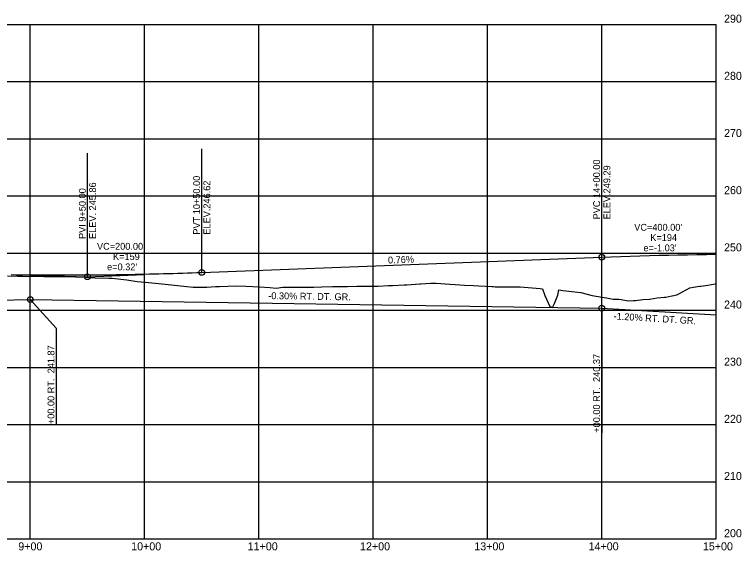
# Model space of a CAD drawing. Extents: x 1939726 to 1943270, y 529766 to 530234.
# Drawn here: x 1940634 to 1941270, y 529766 to 530234 of the extents above; entities that cross this region are included whole.
import ezdxf

# ---------------------------------------------------------------- set-up
doc = ezdxf.new("R2010")
doc.units = 0
for name, color, linetype in [('R_Axis', 7, 'Continuous'), ('R_Axis Annot', 7, 'Continuous'), ('R_Exist Surface', 7, 'Continuous'), ('R_Grid', 7, 'Continuous'), ('R_Vert Alg', 7, 'Continuous'), ('R_Vert Alg Annot', 7, 'Continuous')]:
    doc.layers.add(name, color=color, linetype=linetype)

msp = doc.modelspace()

# ---------------------------------------------------------------- linework, layer by layer
at = {"layer": 'R_Axis'}
for p, q in [((1941247.77, 529775.76), (1941247.77, 530225.76)), ((1939747.77, 529775.76), (1941247.77, 529775.76))]:
    msp.add_line(p, q, dxfattribs=at)
at = {"layer": 'R_Exist Surface'}
msp.add_lwpolyline([(1940627.77, 530005.8), (1940636.75, 530005.67), (1940640.9, 530005.6), (1940659.63, 530005.31), (1940664.83, 530005.26), (1940687.25, 530004.95), (1940687.86, 530004.95), (1940688.32, 530004.94), (1940691.25, 530004.9), (1940704.34, 530004.01), (1940716.35, 530003.94), (1940719.27, 530003.83), (1940732.12, 530002.43), (1940741.34, 530001), (1940748.42, 530000.24), (1940765.86, 529998.64), (1940784.61, 529996.48), (1940790.29, 529995.93), (1940802.24, 529995.86), (1940809.92, 529996.46), (1940813.31, 529996.37), (1940827.78, 529997.04), (1940836.26, 529996.77), (1940848.19, 529996.17), (1940857.32, 529995.78), (1940862.81, 529995.19), (1940868.85, 529995.97), (1940880.27, 529995.8), (1940885.88, 529995.98), (1940895.89, 529995.85), (1940902.97, 529996.15), (1940912.22, 529996.48), (1940925.27, 529996.47), (1940933.34, 529996.7), (1940947.49, 529996.7), (1940952.2, 529996.78), (1940961.16, 529997.29), (1940964.65, 529997.36), (1940974.86, 529997.97), (1940977.1, 529998.02), (1940988.59, 529998.76), (1940989.53, 529998.78), (1940998.16, 529999.37), (1941002.29, 529999.53), (1941002.96, 529999.49), (1941014.89, 529998.62), (1941019.38, 529998.36), (1941027.58, 529997.79), (1941035.53, 529997.36), (1941040.35, 529997.05), (1941051.46, 529996.48), (1941053.2, 529996.37), (1941054.47, 529996.33), (1941074.38, 529996.18), (1941074.49, 529996.18), (1941076.43, 529996.17), (1941093.85, 529994.83), (1941096.03, 529994.5), (1941097.97, 529988.68), (1941102.22, 529978.97), (1941104.74, 529978.09), (1941106.43, 529981.74), (1941109.22, 529988.81), (1941110.27, 529993.58), (1941113.6, 529992.96), (1941129.61, 529991.18), (1941139.51, 529988.51), (1941149.85, 529987.03), (1941151.94, 529986.62), (1941157.76, 529985.53), (1941158.28, 529985.51), (1941162.61, 529985.38), (1941164.62, 529985.03), (1941170.96, 529984.06), (1941170.98, 529984.06), (1941175.58, 529984.14), (1941177.31, 529984.32), (1941183.62, 529985.15), (1941183.65, 529985.15), (1941189.42, 529985.48), (1941189.99, 529985.56), (1941196.33, 529986.58), (1941196.37, 529986.59), (1941202.67, 529987.16), (1941203.77, 529987.29), (1941209.02, 529988.27), (1941209.3, 529988.33), (1941213.39, 529989.18), (1941215.36, 529990.22), (1941221.7, 529993.7), (1941224.71, 529995.43), (1941228.04, 529995.92), (1941231.69, 529996.47), (1941233.62, 529996.71), (1941234.38, 529996.82), (1941240.72, 529997.78), (1941247.07, 529998.77), (1941247.77, 529998.88)], dxfattribs=at)
at = {"layer": 'R_Grid'}
for p, q in [((1939747.77, 530225.76), (1941247.77, 530225.76)), ((1939747.77, 530225.76), (1941247.77, 530225.76)), ((1940647.77, 529775.76), (1940647.77, 530225.76)), ((1940747.77, 529775.76), (1940747.77, 530225.76)), ((1940847.77, 529775.76), (1940847.77, 530225.76)), ((1940947.77, 529775.76), (1940947.77, 530225.76)), ((1941047.77, 529775.76), (1941047.77, 530225.76)), ((1941147.77, 529775.76), (1941147.77, 530225.76)), ((1939747.77, 530175.76), (1941247.77, 530175.76)), ((1939747.77, 530125.76), (1941247.77, 530125.76)), ((1939747.77, 530075.76), (1941247.77, 530075.76)), ((1939747.77, 530025.76), (1941247.77, 530025.76)), ((1939747.77, 529975.76), (1941247.77, 529975.76)), ((1939747.77, 529925.76), (1941247.77, 529925.76)), ((1939747.77, 529875.76), (1941247.77, 529875.76)), ((1939747.77, 529825.76), (1941247.77, 529825.76))]:
    msp.add_line(p, q, dxfattribs=at)
at = {"layer": 'R_Vert Alg'}
for p, q in [((1940797.77, 530008.86), (1941147.77, 530022.19)), ((1940647.77, 530006.31), (1940697.77, 530005.06)), ((1940697.77, 530005.06), (1940747.77, 530006.96)), ((1940147.77, 529975.11), (1940647.77, 529985.11)), ((1940647.77, 529985.11), (1941147.77, 529977.61)), ((1941147.77, 529977.61), (1941247.77, 529971.61))]:
    msp.add_line(p, q, dxfattribs=at)
for points in [[(1941147.77, 530022.19), (1941156.1, 530022.5), (1941164.43, 530022.79), (1941172.77, 530023.06), (1941181.1, 530023.32), (1941189.43, 530023.55), (1941197.77, 530023.77), (1941206.1, 530023.97), (1941214.43, 530024.16), (1941222.77, 530024.32), (1941231.1, 530024.47), (1941239.43, 530024.6), (1941247.77, 530024.71)], [(1940631.1, 530006.9), (1940635.27, 530006.84), (1940639.43, 530006.79), (1940643.6, 530006.74), (1940647.77, 530006.7), (1940651.93, 530006.66), (1940656.1, 530006.63), (1940660.27, 530006.61), (1940664.43, 530006.59), (1940668.6, 530006.58), (1940672.77, 530006.57), (1940676.93, 530006.57), (1940681.1, 530006.57), (1940685.27, 530006.58), (1940689.43, 530006.59), (1940693.6, 530006.61), (1940701.93, 530006.66), (1940706.1, 530006.7), (1940710.27, 530006.74), (1940714.43, 530006.79), (1940718.6, 530006.84), (1940722.77, 530006.9), (1940726.93, 530006.96), (1940731.1, 530007.03), (1940735.27, 530007.1), (1940739.43, 530007.18), (1940743.6, 530007.26), (1940747.77, 530007.35), (1940751.93, 530007.45), (1940756.1, 530007.55), (1940760.27, 530007.66), (1940764.43, 530007.77), (1940768.6, 530007.89), (1940772.77, 530008.01), (1940776.93, 530008.14), (1940781.1, 530008.27), (1940785.27, 530008.41), (1940789.43, 530008.56), (1940793.6, 530008.71), (1940797.77, 530008.86)]]:
    msp.add_lwpolyline(points, dxfattribs=at)
for centre in [(1940647.77, 529985.11), (1941147.77, 529977.61)]:
    msp.add_circle(centre, 2.5, dxfattribs=at)
at = {"layer": 'R_Vert Alg Annot'}
for p, q in [((1941147.77, 530052.19), (1941147.77, 530130.19)), ((1940697.77, 530035.06), (1940697.77, 530113.06)), ((1940797.77, 530038.86), (1940797.77, 530116.86)), ((1941147.77, 530022.19), (1941147.77, 530052.19)), ((1940797.77, 530008.86), (1940797.77, 530038.86)), ((1940697.77, 530005.06), (1940697.77, 530035.06)), ((1940647.77, 529985.11), (1940670.38, 529960.11)), ((1941147.77, 529977.61), (1941147.77, 529952.61)), ((1940670.38, 529960.11), (1940670.38, 529876.11)), ((1941147.77, 529952.61), (1941147.77, 529868.61))]:
    msp.add_line(p, q, dxfattribs=at)
for centre in [(1941147.77, 530022.19), (1940797.77, 530008.86), (1940697.77, 530005.06)]:
    msp.add_circle(centre, 2.5, dxfattribs=at)

# ---------------------------------------------------------------- texts
at = {"layer": 'R_Axis Annot'}
for s, p in [('290', (1941254.77, 530227.26)), ('290', (1941254.77, 530227.26)), ('280', (1941254.77, 530177.26)), ('270', (1941254.77, 530127.26)), ('260', (1941254.77, 530077.26)), ('250', (1941254.77, 530027.26)), ('240', (1941254.77, 529977.26)), ('230', (1941254.77, 529927.26)), ('220', (1941254.77, 529877.26)), ('210', (1941254.77, 529827.26)), ('200', (1941254.77, 529777.26)), ('9+00', (1940637.25, 529765.76)), ('10+00', (1940736.03, 529765.76)), ('11+00', (1940837.96, 529765.76)), ('12+00', (1940936.26, 529765.76)), ('13+00', (1941036.26, 529765.76)), ('14+00', (1941136.26, 529765.76)), ('15+00', (1941236.26, 529765.76))]:
    msp.add_text(s, height=7, dxfattribs=at).set_placement(p)
at = {"layer": 'R_Vert Alg Annot'}
for s, rotation, p in [('PVC 14+00.00', 90, (1941146.27, 530055.19)), ('ELEV.249.29', 90, (1941155.27, 530055.19)), ('PVT 10+50.00', 90, (1940796.27, 530041.86)), ('ELEV.246.62', 90, (1940805.27, 530041.86)), ('PVI 9+50.00', 90, (1940696.27, 530038.06)), ('ELEV. 245.86', 90, (1940705.27, 530038.06)), ('0.76%', 2.18059, (1940960.84, 530016.57)), ('-0.30% RT. DT. GR.', 359.14029, (1940855.93, 529985.49)), ('-1.20% RT. DT. GR.', 356.56637, (1941158.01, 529967.74)), ('+00.00 RT.  241.87', 90, (1940668.88, 529876.11)), ('+00.00 RT.  240.37', 90, (1941146.27, 529868.61))]:
    msp.add_text(s, height=6, rotation=rotation, dxfattribs=at).set_placement(p)
for s, p in [("VC=400.00'", (1941176.2, 530045.29)), ('K=194', (1941190.23, 530036.29)), ("VC=200.00'", (1940706.12, 530028.66)), ("e=-1.03'", (1941184.28, 530027.29)), ('K=159', (1940720.13, 530019.66)), ("e=0.32'", (1940714.96, 530010.66))]:
    msp.add_text(s, height=6, dxfattribs=at).set_placement(p)

doc.saveas('drawing.dxf')
